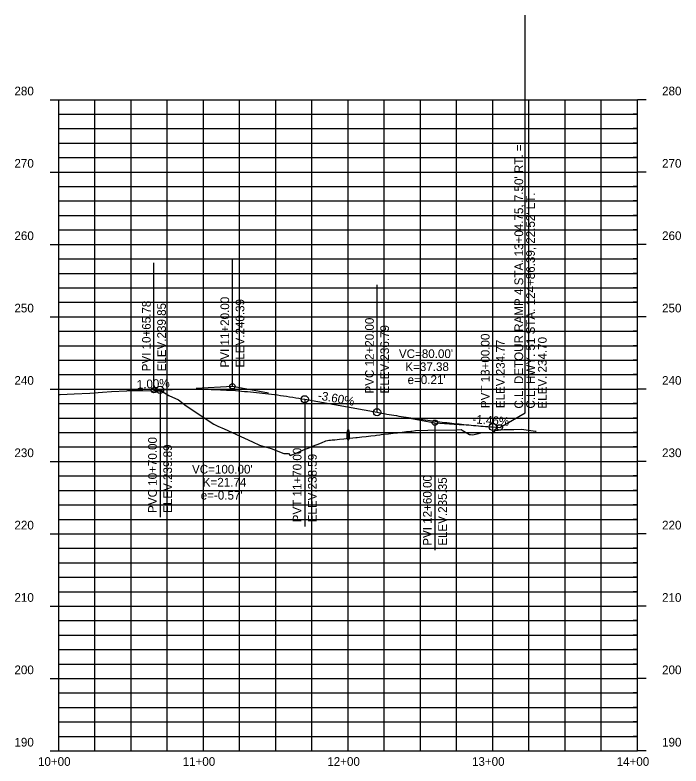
# Model space of a CAD drawing. Extents: x 921603 to 924670, y 1759276 to 1766491.
# Drawn here: x 921610 to 922070, y 1759922 to 1760441 of the extents above; entities that cross this region are included whole.
import ezdxf

# ---------------------------------------------------------------- set-up
doc = ezdxf.new("R2010")
doc.units = 0
for name, color, linetype in [('63', 7, 'Continuous'), ('R_Axis_Annotation', 7, 'Continuous'), ('R_Drainage', 7, 'Continuous'), ('R_Exist Surface', 7, 'Continuous'), ('R_Grid', 7, 'Continuous'), ('R_Grid Annot', 7, 'Continuous'), ('R_Grid_Minor', 7, 'Continuous'), ('R_Vert Alg', 7, 'Continuous'), ('R_Vert Alg Annot', 7, 'Continuous')]:
    doc.layers.add(name, color=color, linetype=linetype)

msp = doc.modelspace()

# ---------------------------------------------------------------- linework, layer by layer
at = {"layer": 'R_Drainage'}
msp.add_ellipse((921839.83, 1760150.56), major_axis=(0, 3.75), ratio=0.2, dxfattribs=at)
at = {"layer": 'R_Exist Surface'}
msp.add_lwpolyline([(921639.83, 1760178.5), (921640.7, 1760178.53), (921650.5, 1760178.94), (921661.21, 1760179.53), (921670.12, 1760180.1), (921676.23, 1760180.61), (921686.66, 1760181.17), (921686.9, 1760181.18), (921687.46, 1760181.22), (921697.82, 1760181.24), (921709.89, 1760180.91), (921710.4, 1760180.9), (921710.88, 1760180.89), (921711.05, 1760180.83), (921712.94, 1760179.78), (921716, 1760177.94), (921722.6, 1760174.75), (921727.82, 1760170.69), (921747.05, 1760158.12), (921749.68, 1760156.72), (921754.05, 1760154.87), (921773.68, 1760145.76), (921778.57, 1760143.49), (921786.53, 1760141.14), (921795.32, 1760137.84), (921798.65, 1760137.65), (921799.76, 1760136.27), (921799.82, 1760136.19), (921800.09, 1760136.34), (921801, 1760136.74), (921802.85, 1760137.56), (921805.95, 1760138.89), (921809.04, 1760140.2), (921812.13, 1760141.49), (921813.83, 1760142.18), (921815.23, 1760142.76), (921818.32, 1760144), (921821.41, 1760145.22), (921824.51, 1760146.41), (921825.46, 1760146.78), (921826.43, 1760146.87), (921827.6, 1760146.99), (921828.86, 1760147.11), (921830.69, 1760147.3), (921833.79, 1760147.62), (921836.88, 1760147.94), (921839.97, 1760148.26), (921840.97, 1760148.37), (921843.07, 1760148.59), (921845.12, 1760148.81), (921846.16, 1760148.92), (921849.25, 1760149.26), (921852.35, 1760149.61), (921855.44, 1760149.95), (921858.53, 1760150.3), (921859.48, 1760150.41), (921861.63, 1760150.66), (921862.71, 1760150.78), (921864.72, 1760151.02), (921864.95, 1760151.04), (921867.81, 1760151.38), (921870.9, 1760151.75), (921874, 1760152.11), (921877.09, 1760152.49), (921880.18, 1760152.87), (921880.88, 1760152.95), (921883.28, 1760153.25), (921883.82, 1760153.31), (921886.35, 1760153.63), (921894.88, 1760153.85), (921914.69, 1760154.23), (921918.06, 1760154.28), (921918.7, 1760153.91), (921923.63, 1760150.9), (921924.35, 1760150.78), (921925.77, 1760150.57), (921928.91, 1760151.44), (921932.43, 1760152.38), (921938.96, 1760152.08), (921939.36, 1760152.06), (921941.18, 1760153.35), (921941.5, 1760153.57), (921941.51, 1760153.58), (921941.55, 1760153.58), (921947.45, 1760154.29), (921954.4, 1760154.41), (921959.69, 1760154.64), (921969.33, 1760153.27), (921969.85, 1760153.2)], dxfattribs=at)
at = {"layer": 'R_Grid'}
for p, q in [((921639.83, 1759932.26), (921639.83, 1760382.26)), ((921639.83, 1760382.26), (922039.83, 1760382.26)), ((921639.83, 1760382.26), (922039.83, 1760382.26)), ((921739.83, 1759932.26), (921739.83, 1760382.26)), ((921839.83, 1759932.26), (921839.83, 1760382.26)), ((921939.83, 1759932.26), (921939.83, 1760382.26)), ((922039.83, 1759932.26), (922039.83, 1760382.26)), ((921639.83, 1760332.26), (922039.83, 1760332.26)), ((921639.83, 1760282.26), (922039.83, 1760282.26)), ((921639.83, 1760232.26), (922039.83, 1760232.26)), ((921639.83, 1760182.26), (922039.83, 1760182.26)), ((921639.83, 1760132.26), (922039.83, 1760132.26)), ((921639.83, 1760082.26), (922039.83, 1760082.26)), ((921639.83, 1760032.26), (922039.83, 1760032.26)), ((921639.83, 1759982.26), (922039.83, 1759982.26)), ((921639.83, 1759932.26), (922039.83, 1759932.26))]:
    msp.add_line(p, q, dxfattribs=at)
at = {"layer": 'R_Grid Annot'}
for p, q in [((921633.83, 1760382.26), (921639.83, 1760382.26)), ((921633.83, 1760382.26), (921639.83, 1760382.26)), ((922045.83, 1760382.26), (922039.83, 1760382.26)), ((922045.83, 1760382.26), (922039.83, 1760382.26)), ((921639.83, 1760372.26), (921642.83, 1760372.26)), ((922039.83, 1760372.26), (922036.83, 1760372.26)), ((921639.83, 1760362.26), (921642.83, 1760362.26)), ((922039.83, 1760362.26), (922036.83, 1760362.26)), ((921639.83, 1760352.26), (921642.83, 1760352.26)), ((922039.83, 1760352.26), (922036.83, 1760352.26)), ((921639.83, 1760342.26), (921642.83, 1760342.26)), ((922039.83, 1760342.26), (922036.83, 1760342.26)), ((921633.83, 1760332.26), (921639.83, 1760332.26)), ((922045.83, 1760332.26), (922039.83, 1760332.26)), ((921639.83, 1760322.26), (921642.83, 1760322.26)), ((922039.83, 1760322.26), (922036.83, 1760322.26)), ((921639.83, 1760312.26), (921642.83, 1760312.26)), ((922039.83, 1760312.26), (922036.83, 1760312.26)), ((921639.83, 1760302.26), (921642.83, 1760302.26)), ((922039.83, 1760302.26), (922036.83, 1760302.26)), ((921639.83, 1760292.26), (921642.83, 1760292.26)), ((922039.83, 1760292.26), (922036.83, 1760292.26)), ((921633.83, 1760282.26), (921639.83, 1760282.26)), ((922045.83, 1760282.26), (922039.83, 1760282.26)), ((921639.83, 1760272.26), (921642.83, 1760272.26)), ((922039.83, 1760272.26), (922036.83, 1760272.26)), ((921639.83, 1760262.26), (921642.83, 1760262.26)), ((922039.83, 1760262.26), (922036.83, 1760262.26)), ((921639.83, 1760252.26), (921642.83, 1760252.26)), ((922039.83, 1760252.26), (922036.83, 1760252.26)), ((921639.83, 1760242.26), (921642.83, 1760242.26)), ((922039.83, 1760242.26), (922036.83, 1760242.26)), ((921633.83, 1760232.26), (921639.83, 1760232.26)), ((922045.83, 1760232.26), (922039.83, 1760232.26)), ((921639.83, 1760222.26), (921642.83, 1760222.26)), ((922039.83, 1760222.26), (922036.83, 1760222.26)), ((921639.83, 1760212.26), (921642.83, 1760212.26)), ((922039.83, 1760212.26), (922036.83, 1760212.26)), ((921639.83, 1760202.26), (921642.83, 1760202.26)), ((922039.83, 1760202.26), (922036.83, 1760202.26)), ((921639.83, 1760192.26), (921642.83, 1760192.26)), ((922039.83, 1760192.26), (922036.83, 1760192.26)), ((921633.83, 1760182.26), (921639.83, 1760182.26)), ((922045.83, 1760182.26), (922039.83, 1760182.26)), ((921639.83, 1760172.26), (921642.83, 1760172.26)), ((922039.83, 1760172.26), (922036.83, 1760172.26)), ((921639.83, 1760162.26), (921642.83, 1760162.26)), ((922039.83, 1760162.26), (922036.83, 1760162.26)), ((921639.83, 1760152.26), (921642.83, 1760152.26)), ((922039.83, 1760152.26), (922036.83, 1760152.26)), ((921639.83, 1760142.26), (921642.83, 1760142.26)), ((922039.83, 1760142.26), (922036.83, 1760142.26)), ((921633.83, 1760132.26), (921639.83, 1760132.26)), ((922045.83, 1760132.26), (922039.83, 1760132.26)), ((921639.83, 1760122.26), (921642.83, 1760122.26)), ((922039.83, 1760122.26), (922036.83, 1760122.26)), ((921639.83, 1760112.26), (921642.83, 1760112.26)), ((922039.83, 1760112.26), (922036.83, 1760112.26)), ((921639.83, 1760102.26), (921642.83, 1760102.26)), ((922039.83, 1760102.26), (922036.83, 1760102.26)), ((921639.83, 1760092.26), (921642.83, 1760092.26)), ((922039.83, 1760092.26), (922036.83, 1760092.26)), ((921633.83, 1760082.26), (921639.83, 1760082.26)), ((922045.83, 1760082.26), (922039.83, 1760082.26)), ((921639.83, 1760072.26), (921642.83, 1760072.26)), ((922039.83, 1760072.26), (922036.83, 1760072.26)), ((921639.83, 1760062.26), (921642.83, 1760062.26)), ((922039.83, 1760062.26), (922036.83, 1760062.26)), ((921639.83, 1760052.26), (921642.83, 1760052.26)), ((922039.83, 1760052.26), (922036.83, 1760052.26)), ((921639.83, 1760042.26), (921642.83, 1760042.26)), ((922039.83, 1760042.26), (922036.83, 1760042.26)), ((921633.83, 1760032.26), (921639.83, 1760032.26)), ((922045.83, 1760032.26), (922039.83, 1760032.26)), ((921639.83, 1760022.26), (921642.83, 1760022.26)), ((922039.83, 1760022.26), (922036.83, 1760022.26)), ((921639.83, 1760012.26), (921642.83, 1760012.26)), ((922039.83, 1760012.26), (922036.83, 1760012.26)), ((921639.83, 1760002.26), (921642.83, 1760002.26)), ((922039.83, 1760002.26), (922036.83, 1760002.26)), ((921639.83, 1759992.26), (921642.83, 1759992.26)), ((922039.83, 1759992.26), (922036.83, 1759992.26)), ((921633.83, 1759982.26), (921639.83, 1759982.26)), ((922045.83, 1759982.26), (922039.83, 1759982.26)), ((921639.83, 1759972.26), (921642.83, 1759972.26)), ((922039.83, 1759972.26), (922036.83, 1759972.26)), ((921639.83, 1759962.26), (921642.83, 1759962.26)), ((922039.83, 1759962.26), (922036.83, 1759962.26)), ((921639.83, 1759952.26), (921642.83, 1759952.26)), ((922039.83, 1759952.26), (922036.83, 1759952.26)), ((921639.83, 1759942.26), (921642.83, 1759942.26)), ((922039.83, 1759942.26), (922036.83, 1759942.26)), ((921633.83, 1759932.26), (921639.83, 1759932.26)), ((922045.83, 1759932.26), (922039.83, 1759932.26))]:
    msp.add_line(p, q, dxfattribs=at)
at = {"layer": 'R_Grid_Minor'}
for p, q in [((921664.83, 1759932.26), (921664.83, 1760382.26)), ((921689.83, 1759932.26), (921689.83, 1760382.26)), ((921714.83, 1759932.26), (921714.83, 1760382.26)), ((921764.83, 1759932.26), (921764.83, 1760382.26)), ((921789.83, 1759932.26), (921789.83, 1760382.26)), ((921814.83, 1759932.26), (921814.83, 1760382.26)), ((921864.83, 1759932.26), (921864.83, 1760382.26)), ((921889.83, 1759932.26), (921889.83, 1760382.26)), ((921914.83, 1759932.26), (921914.83, 1760382.26)), ((921964.83, 1759932.26), (921964.83, 1760382.26)), ((921989.83, 1759932.26), (921989.83, 1760382.26)), ((922014.83, 1759932.26), (922014.83, 1760382.26)), ((921639.83, 1760372.26), (922039.83, 1760372.26)), ((921639.83, 1760362.26), (922039.83, 1760362.26)), ((921639.83, 1760352.26), (922039.83, 1760352.26)), ((921639.83, 1760342.26), (922039.83, 1760342.26)), ((921639.83, 1760322.26), (922039.83, 1760322.26)), ((921639.83, 1760312.26), (922039.83, 1760312.26)), ((921639.83, 1760302.26), (922039.83, 1760302.26)), ((921639.83, 1760292.26), (922039.83, 1760292.26)), ((921639.83, 1760272.26), (922039.83, 1760272.26)), ((921639.83, 1760262.26), (922039.83, 1760262.26)), ((921639.83, 1760252.26), (922039.83, 1760252.26)), ((921639.83, 1760242.26), (922039.83, 1760242.26)), ((921639.83, 1760222.26), (922039.83, 1760222.26)), ((921639.83, 1760212.26), (922039.83, 1760212.26)), ((921639.83, 1760202.26), (922039.83, 1760202.26)), ((921639.83, 1760192.26), (922039.83, 1760192.26)), ((921639.83, 1760172.26), (922039.83, 1760172.26)), ((921639.83, 1760162.26), (922039.83, 1760162.26)), ((921639.83, 1760152.26), (922039.83, 1760152.26)), ((921639.83, 1760142.26), (922039.83, 1760142.26)), ((921639.83, 1760122.26), (922039.83, 1760122.26)), ((921639.83, 1760112.26), (922039.83, 1760112.26)), ((921639.83, 1760102.26), (922039.83, 1760102.26)), ((921639.83, 1760092.26), (922039.83, 1760092.26)), ((921639.83, 1760072.26), (922039.83, 1760072.26)), ((921639.83, 1760062.26), (922039.83, 1760062.26)), ((921639.83, 1760052.26), (922039.83, 1760052.26)), ((921639.83, 1760042.26), (922039.83, 1760042.26)), ((921639.83, 1760022.26), (922039.83, 1760022.26)), ((921639.83, 1760012.26), (922039.83, 1760012.26)), ((921639.83, 1760002.26), (922039.83, 1760002.26)), ((921639.83, 1759992.26), (922039.83, 1759992.26)), ((921639.83, 1759972.26), (922039.83, 1759972.26)), ((921639.83, 1759962.26), (922039.83, 1759962.26)), ((921639.83, 1759952.26), (922039.83, 1759952.26)), ((921639.83, 1759942.26), (922039.83, 1759942.26))]:
    msp.add_line(p, q, dxfattribs=at)
at = {"layer": 'R_Vert Alg'}
for p, q in [((921705.61, 1760181.51), (921709.83, 1760181.72)), ((921809.83, 1760175.22), (921859.83, 1760166.22)), ((921939.83, 1760156.11), (921944.58, 1760155.76))]:
    msp.add_line(p, q, dxfattribs=at)
for points in [[(921709.83, 1760181.72), (921711.91, 1760181.82), (921713.99, 1760181.91), (921716.08, 1760181.99), (921718.16, 1760182.06), (921720.24, 1760182.12), (921722.33, 1760182.17), (921724.41, 1760182.21), (921726.49, 1760182.23), (921728.58, 1760182.25), (921730.66, 1760182.26), (921732.74, 1760182.26), (921734.83, 1760182.25), (921736.91, 1760182.23), (921738.99, 1760182.2), (921741.08, 1760182.16), (921743.16, 1760182.11), (921745.24, 1760182.05), (921747.33, 1760181.98), (921749.41, 1760181.9), (921751.49, 1760181.81), (921753.58, 1760181.71), (921755.66, 1760181.6), (921757.74, 1760181.48), (921761.91, 1760181.21), (921763.99, 1760181.05), (921766.08, 1760180.89), (921768.16, 1760180.72), (921770.24, 1760180.54), (921772.33, 1760180.35), (921774.41, 1760180.15), (921776.49, 1760179.94), (921778.58, 1760179.72), (921780.66, 1760179.49), (921782.74, 1760179.25), (921784.83, 1760179), (921786.91, 1760178.74), (921788.99, 1760178.47), (921791.08, 1760178.19), (921793.16, 1760177.9), (921795.24, 1760177.6), (921797.33, 1760177.29), (921799.41, 1760176.97), (921801.49, 1760176.64), (921803.58, 1760176.3), (921805.66, 1760175.95), (921807.74, 1760175.59), (921809.83, 1760175.22)], [(921859.83, 1760166.22), (921861.49, 1760165.92), (921863.16, 1760165.63), (921864.83, 1760165.34), (921866.49, 1760165.05), (921868.16, 1760164.77), (921869.83, 1760164.49), (921871.49, 1760164.21), (921873.16, 1760163.94), (921874.83, 1760163.67), (921876.49, 1760163.41), (921878.16, 1760163.15), (921879.83, 1760162.89), (921881.49, 1760162.63), (921883.16, 1760162.39), (921884.83, 1760162.14), (921886.49, 1760161.9), (921888.16, 1760161.66), (921889.83, 1760161.42), (921891.49, 1760161.19), (921893.16, 1760160.96), (921894.83, 1760160.74), (921896.49, 1760160.52), (921898.16, 1760160.3), (921901.49, 1760159.88), (921903.16, 1760159.68), (921904.83, 1760159.48), (921906.49, 1760159.28), (921908.16, 1760159.08), (921909.83, 1760158.89), (921911.49, 1760158.71), (921913.16, 1760158.53), (921914.83, 1760158.35), (921916.49, 1760158.17), (921918.16, 1760158), (921919.83, 1760157.83), (921921.49, 1760157.67), (921923.16, 1760157.51), (921924.83, 1760157.35), (921926.49, 1760157.2), (921928.16, 1760157.05), (921929.83, 1760156.9), (921931.49, 1760156.76), (921933.16, 1760156.62), (921934.83, 1760156.49), (921936.49, 1760156.36), (921938.16, 1760156.23), (921939.83, 1760156.11)]]:
    msp.add_lwpolyline(points, dxfattribs=at)
at = {"layer": 'R_Vert Alg Annot'}
for p, q in [((921962.3, 1760165.76), (921962.3, 1760440.77)), ((921759.83, 1760194.22), (921759.83, 1760272.22)), ((921705.61, 1760191.51), (921705.61, 1760269.51)), ((921859.83, 1760176.22), (921859.83, 1760254.22)), ((921939.83, 1760166.11), (921939.83, 1760244.11)), ((921759.83, 1760184.22), (921759.83, 1760194.22)), ((921705.61, 1760181.51), (921705.61, 1760191.51)), ((921709.83, 1760181.72), (921709.83, 1760171.72)), ((921734.83, 1760182.97), (921759.83, 1760184.22)), ((921759.83, 1760184.22), (921784.83, 1760179.72)), ((921859.83, 1760166.22), (921859.83, 1760176.22)), ((921709.83, 1760171.72), (921709.83, 1760093.72)), ((921809.83, 1760175.22), (921809.83, 1760165.22)), ((921939.83, 1760156.11), (921939.83, 1760166.11)), ((921809.83, 1760165.22), (921809.83, 1760087.22)), ((921879.83, 1760162.62), (921899.83, 1760159.02)), ((921944.58, 1760155.76), (921962.3, 1760165.76)), ((921899.83, 1760159.02), (921919.83, 1760157.56)), ((921899.83, 1760159.02), (921899.83, 1760149.02)), ((921899.83, 1760149.02), (921899.83, 1760071.02))]:
    msp.add_line(p, q, dxfattribs=at)
for centre, radius in [((921705.61, 1760181.51), 1.85), ((921709.83, 1760181.72), 2.5), ((921759.83, 1760184.22), 1.85), ((921809.83, 1760175.22), 2.5), ((921859.83, 1760166.22), 2.5), ((921899.83, 1760159.02), 1.85), ((921939.83, 1760156.11), 2.5), ((921944.58, 1760155.76), 1.85)]:
    msp.add_circle(centre, radius, dxfattribs=at)

# ---------------------------------------------------------------- texts
at = {"layer": '63'}
msp.add_text('-', height=0.0001, dxfattribs=at).set_placement((921639.83, 1759932.26))
at = {"layer": 'R_Axis_Annotation'}
for s, p in [('280', (921609.16, 1760385.26)), ('280', (921609.16, 1760385.26)), ('280', (922056.84, 1760385.26)), ('280', (922056.84, 1760385.26)), ('270', (921609.16, 1760335.26)), ('270', (922056.84, 1760335.26)), ('260', (921609.16, 1760285.26)), ('260', (922056.84, 1760285.26)), ('250', (921609.16, 1760235.26)), ('250', (922056.84, 1760235.26)), ('240', (921609.16, 1760185.26)), ('240', (922056.84, 1760185.26)), ('230', (921609.16, 1760135.26)), ('230', (922056.84, 1760135.26)), ('220', (921609.16, 1760085.26)), ('220', (922056.84, 1760085.26)), ('210', (921609.16, 1760035.26)), ('210', (922056.84, 1760035.26)), ('200', (921609.16, 1759985.26)), ('200', (922056.84, 1759985.26)), ('190', (921609.16, 1759935.26)), ('190', (922056.84, 1759935.26)), ('10+00', (921625.42, 1759921.91)), ('11+00', (921725.42, 1759921.91)), ('12+00', (921825.42, 1759921.91)), ('13+00', (921925.42, 1759921.91)), ('14+00', (922025.42, 1759921.91))]:
    msp.add_text(s, height=6, dxfattribs=at).set_placement(p)
at = {"layer": 'R_Vert Alg Annot'}
for s, rotation, p in [("C.L. DETOUR RAMP 4 STA. 13+04.75, 7.50' RT. =", 90, (921960.79, 1760168.79)), ("C.L. HWY. 51 STA. 124+86.39, 22.52' LT.", 90, (921968.91, 1760168.79)), ('PVI 11+20.00', 90, (921757.58, 1760197.22)), ('ELEV.240.39', 90, (921768.08, 1760197.22)), ('PVI 10+65.78', 90, (921703.36, 1760194.51)), ('ELEV.239.85', 90, (921713.86, 1760194.51)), ('PVC 12+20.00', 90, (921857.58, 1760179.22)), ('ELEV.236.79', 90, (921868.08, 1760179.22)), ('PVT 13+00.00', 90, (921937.58, 1760169.11)), ('ELEV. 234.70', 90, (921977.04, 1760168.79)), ('ELEV.234.77', 90, (921948.08, 1760169.11)), ('1.00%', 2.8624, (921693.86, 1760182.42)), ('-3.60%', 349.796, (921818.56, 1760175.17)), ('-1.46%', 355.8321, (921925.56, 1760158.65)), ('PVC 10+70.00', 90, (921707.58, 1760096.72)), ('ELEV.239.89', 90, (921718.08, 1760096.72)), ('PVT 11+70.00', 90, (921807.58, 1760090.22)), ('ELEV.238.59', 90, (921818.08, 1760090.22)), ('PVI 12+60.00', 90, (921897.58, 1760074.02)), ('ELEV.235.35', 90, (921908.08, 1760074.02))]:
    msp.add_text(s, height=6, rotation=rotation, dxfattribs=at).set_placement(p)
for s, p in [("VC=80.00'", (921874.93, 1760203.74)), ('K=37.38', (921879.37, 1760194.74)), ("e=0.21'", (921880.93, 1760185.74)), ("VC=100.00'", (921731.93, 1760123.91)), ('K=21.74', (921739.35, 1760114.91)), ("e=-0.57'", (921737.93, 1760105.91))]:
    msp.add_text(s, height=6, dxfattribs=at).set_placement(p)

doc.saveas('drawing.dxf')
